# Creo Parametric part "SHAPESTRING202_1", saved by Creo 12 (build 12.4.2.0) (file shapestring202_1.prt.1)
Units: Custom; MM, KILOGRAM, SECS

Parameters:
  PTC_WM_ITERATION = "0"
  PTC_WM_VERSION = "-.0"
  PTC_WM_LIFECYCLE_STATE = "In Work"
  PTC_WM_LIFECYCLE = "MO_CADDocument"
  PTC_WM_CREATED_BY = "Maximilian Roepper (Z0017RMS: MO)"
  PTC_WM_CREATED_ON = "18-Sep-26 11:36:42 AM"
  PTC_WM_MODIFIED_BY = "Maximilian Roepper (Z0017RMS: MO)"
  PTC_WM_MODIFIED_ON = "18-Sep-26 11:36:46 AM"
  PDMLINKNUMBER = "PDM000071454849"
  PTC_WM_NAME = "shapestring202_1.prt"
  PTC_WM_NUMBER = "PDM000071454849"

Other parameters: WEIGHT, WEIGHT_FACTOR, WEIGHT_ADD, _MASS_TEMP, _DIFF_TEMP, MC_ERRORS, SUPPLIER

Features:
  1. coordinate system
  2. datum plane "PRT_YZ"
  3. datum plane "PRT_XY"
  4. datum plane "PRT_XZ"
  5. coordinate system
  6. datum axis
  7. datum axis
  8. datum axis
  9. coordinate system
  10. imported feature

Other named items: PRT, SIEMENS_MO, DRW_VIEW_ORG, PRT_X, PRT_Y, PRT_Z, CS0, ROUGH_GROB

Layers: 00_STD_CSYS-KSYS, 01_STD_PLANES-EBENEN, 02_STD_AXES-ACHSEN, 03_STD_CSYS-KSYS, 24_IMPORT_FEAT-IMPORT_KE, INTFCLR

Surfaces: 1 plane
